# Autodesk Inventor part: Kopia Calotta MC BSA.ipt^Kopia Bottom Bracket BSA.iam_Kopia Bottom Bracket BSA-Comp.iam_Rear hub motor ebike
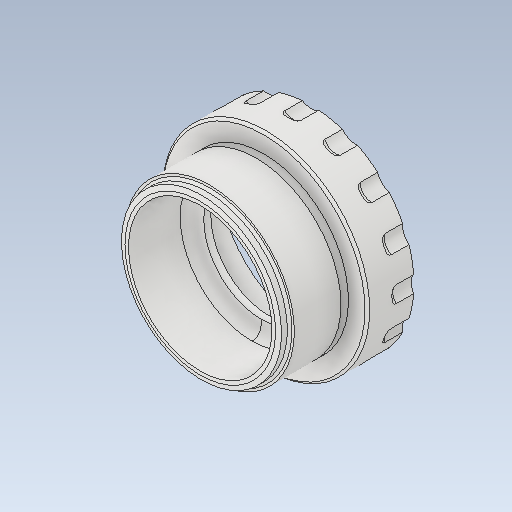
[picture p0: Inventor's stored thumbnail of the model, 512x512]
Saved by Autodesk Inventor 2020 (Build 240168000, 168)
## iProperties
Created: 2017-11
Part Number: Kopia Calotta MC BSA.ipt^Kopia Bottom Bracket BSA.iam_Kopia Bottom Bracket BSA-Comp.iam_Rear hub motor ebike
Material: Ogólny
Document SubType Name: Modeling
Designer: Tomasz
Density: 1 g/cm^3
Appearance: Domyślna
Sending System: SolidWorks 2017
Last Author: Tomasz
Last Saved: 2017-11-19
Author: Tomasz
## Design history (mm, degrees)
feature "Calotta MC BSA.ipt"
node "Bryła1"
